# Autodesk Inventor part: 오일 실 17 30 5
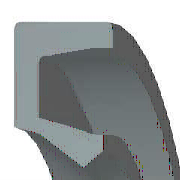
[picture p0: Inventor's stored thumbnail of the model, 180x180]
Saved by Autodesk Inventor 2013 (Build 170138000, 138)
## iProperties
IsCustomPart: 1
Created: 2012-02
Part Number: 오일 실 17 30 5
Material: 고무
Description: 오일 실 - 비스프링, 금속 케이스 GM
Document SubType Name: Modeling
Standard: JIS B 2402
Designer: mduedu
Standards Organization: JIS
Language: ko-KR
Size Designation: 17 30 5 C
Categories: <MemberInstance><Categories><Category DisplayName="샤프트 부품" InternalName="7f7aeb1f-a693-4053-b835-cee3144e0d98" Mnemonic="SHFT"><Category DisplayName="실링" Intern
Density: 0.93 g/cm^3
Author: mduedu
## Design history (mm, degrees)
fillet "모깎기2" dims "d36" = 0.5
body "Solid1"
revolve "회전1" stored, may be unused: angle "d27" = 360 deg
fillet "모깎기1" dims "d28" = 0.25 (= 0.05 x b)
chamfer "모따기1" distance "d29" = 0.07143 (= 0.0142857 x b); stored, may be unused: second distance "d30" = 0.25 (= 0.05 x b), angle "d35" = 45 deg
sketch "스케치2"
  geometry: L1 (-9.367, -3.238)-(-10.233, -3.863); L2 (-8.5, -1.625)-(-9.367, -3.238); L3 (-9.15, -1)-(-8.5, -1.625); L4 (-11.317, -3.75)-(-9.15, -1); L5 (-13.075, -3.75)-(-11.317, -3.75); L6 (-14.375, -1.25)-(-13.075, -3.75); L7 (-14.375, 0)-(-14.375, -1.25); L8 (-15, 0)-(-14.375, 0); L9 (-15, -5)-(-15, 0); L10 (-11.129, -5)-(-15, -5); L11 (-10.233, -3.863)-(-11.129, -5); L12 (0, -9.6)-(0, 1.6) reference; L13 (-14, 0)-(-28, 0) reference
  constraints: 22 end point, 3 horizontal, 2 vertical, 1 parallel
  dimensions: "d2" = 5 distance of L9.start L8.start (= b); "d4" = 1 vertical distance of L8.start L3.start (= 0.2 x b); "d6" = 0.625 distance of L8.start L7.start (= 0.125 x b); "d8" = 1.25 distance of L7.start L6.start (= 0.25 x b); "d10" = 1.25 vertical distance of L5.start L9.start (= 0.25 x b); "d12" = 1.3 horizontal distance of L6.start L5.start (= 0.1 x dd - 0.1 x Diam); "d14" = 1.6129 vertical distance of L2.start L1.start (= 0.322581 x b); "d16" = 0.86667 horizontal distance of L1.start L1.end (= 0.0666667 x dd - 0.0666667 x Diam); "d18" = 0.86667 horizontal distance of L2.start L1.start (= 0.0666667 x dd - 0.0666667 x Diam); "d20" = 0.625 vertical distance of L3.start L2.start (= 0.125 x b); "d22" = 0.65 horizontal distance of L3.start L2.start (= 0.05 x dd - 0.05 x Diam); "d24" = 0.625 vertical distance of L1.start L1.end (= 0.125 x b); "d26" = 2.16667 horizontal distance of L4.start L3.start (= 0.166667 x dd - 0.166667 x Diam); "d31" = 0 distance between parallel lines of L8 L13; "d32" = 15 distance between parallel lines of L12 L9 (= 0.5 x dd); "d33" = 8.5 distance from line of L12 L2.start (= 0.5 x Diam)
other parameters: "Diam" = 17 [user parameter; used in 6 equation terms], "b" = 5 [user parameter; used in 11 equation terms], "d1" = 8 (derived), "d3" = 1.6 (derived), "d5" = 1 (derived), "d7" = 2 (derived), "d9" = 2 (derived), "d11" = 2 (derived), "d13" = 2.58065 (derived), "d15" = 1.33333 (derived), "d17" = 1.33333 (derived), "d19" = 1 (derived), "d21" = 1 (derived), "d23" = 1 (derived), "d25" = 3.33333 (derived), "d34" = 0
